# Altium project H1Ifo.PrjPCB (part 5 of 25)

## Sheet IfoIsc1.SchDoc: D1800185
size C; Engineer: Daniel Sigg; DocumentNumber: 4; Revision: 4; SheetNumber: 4; SheetTotal: 11
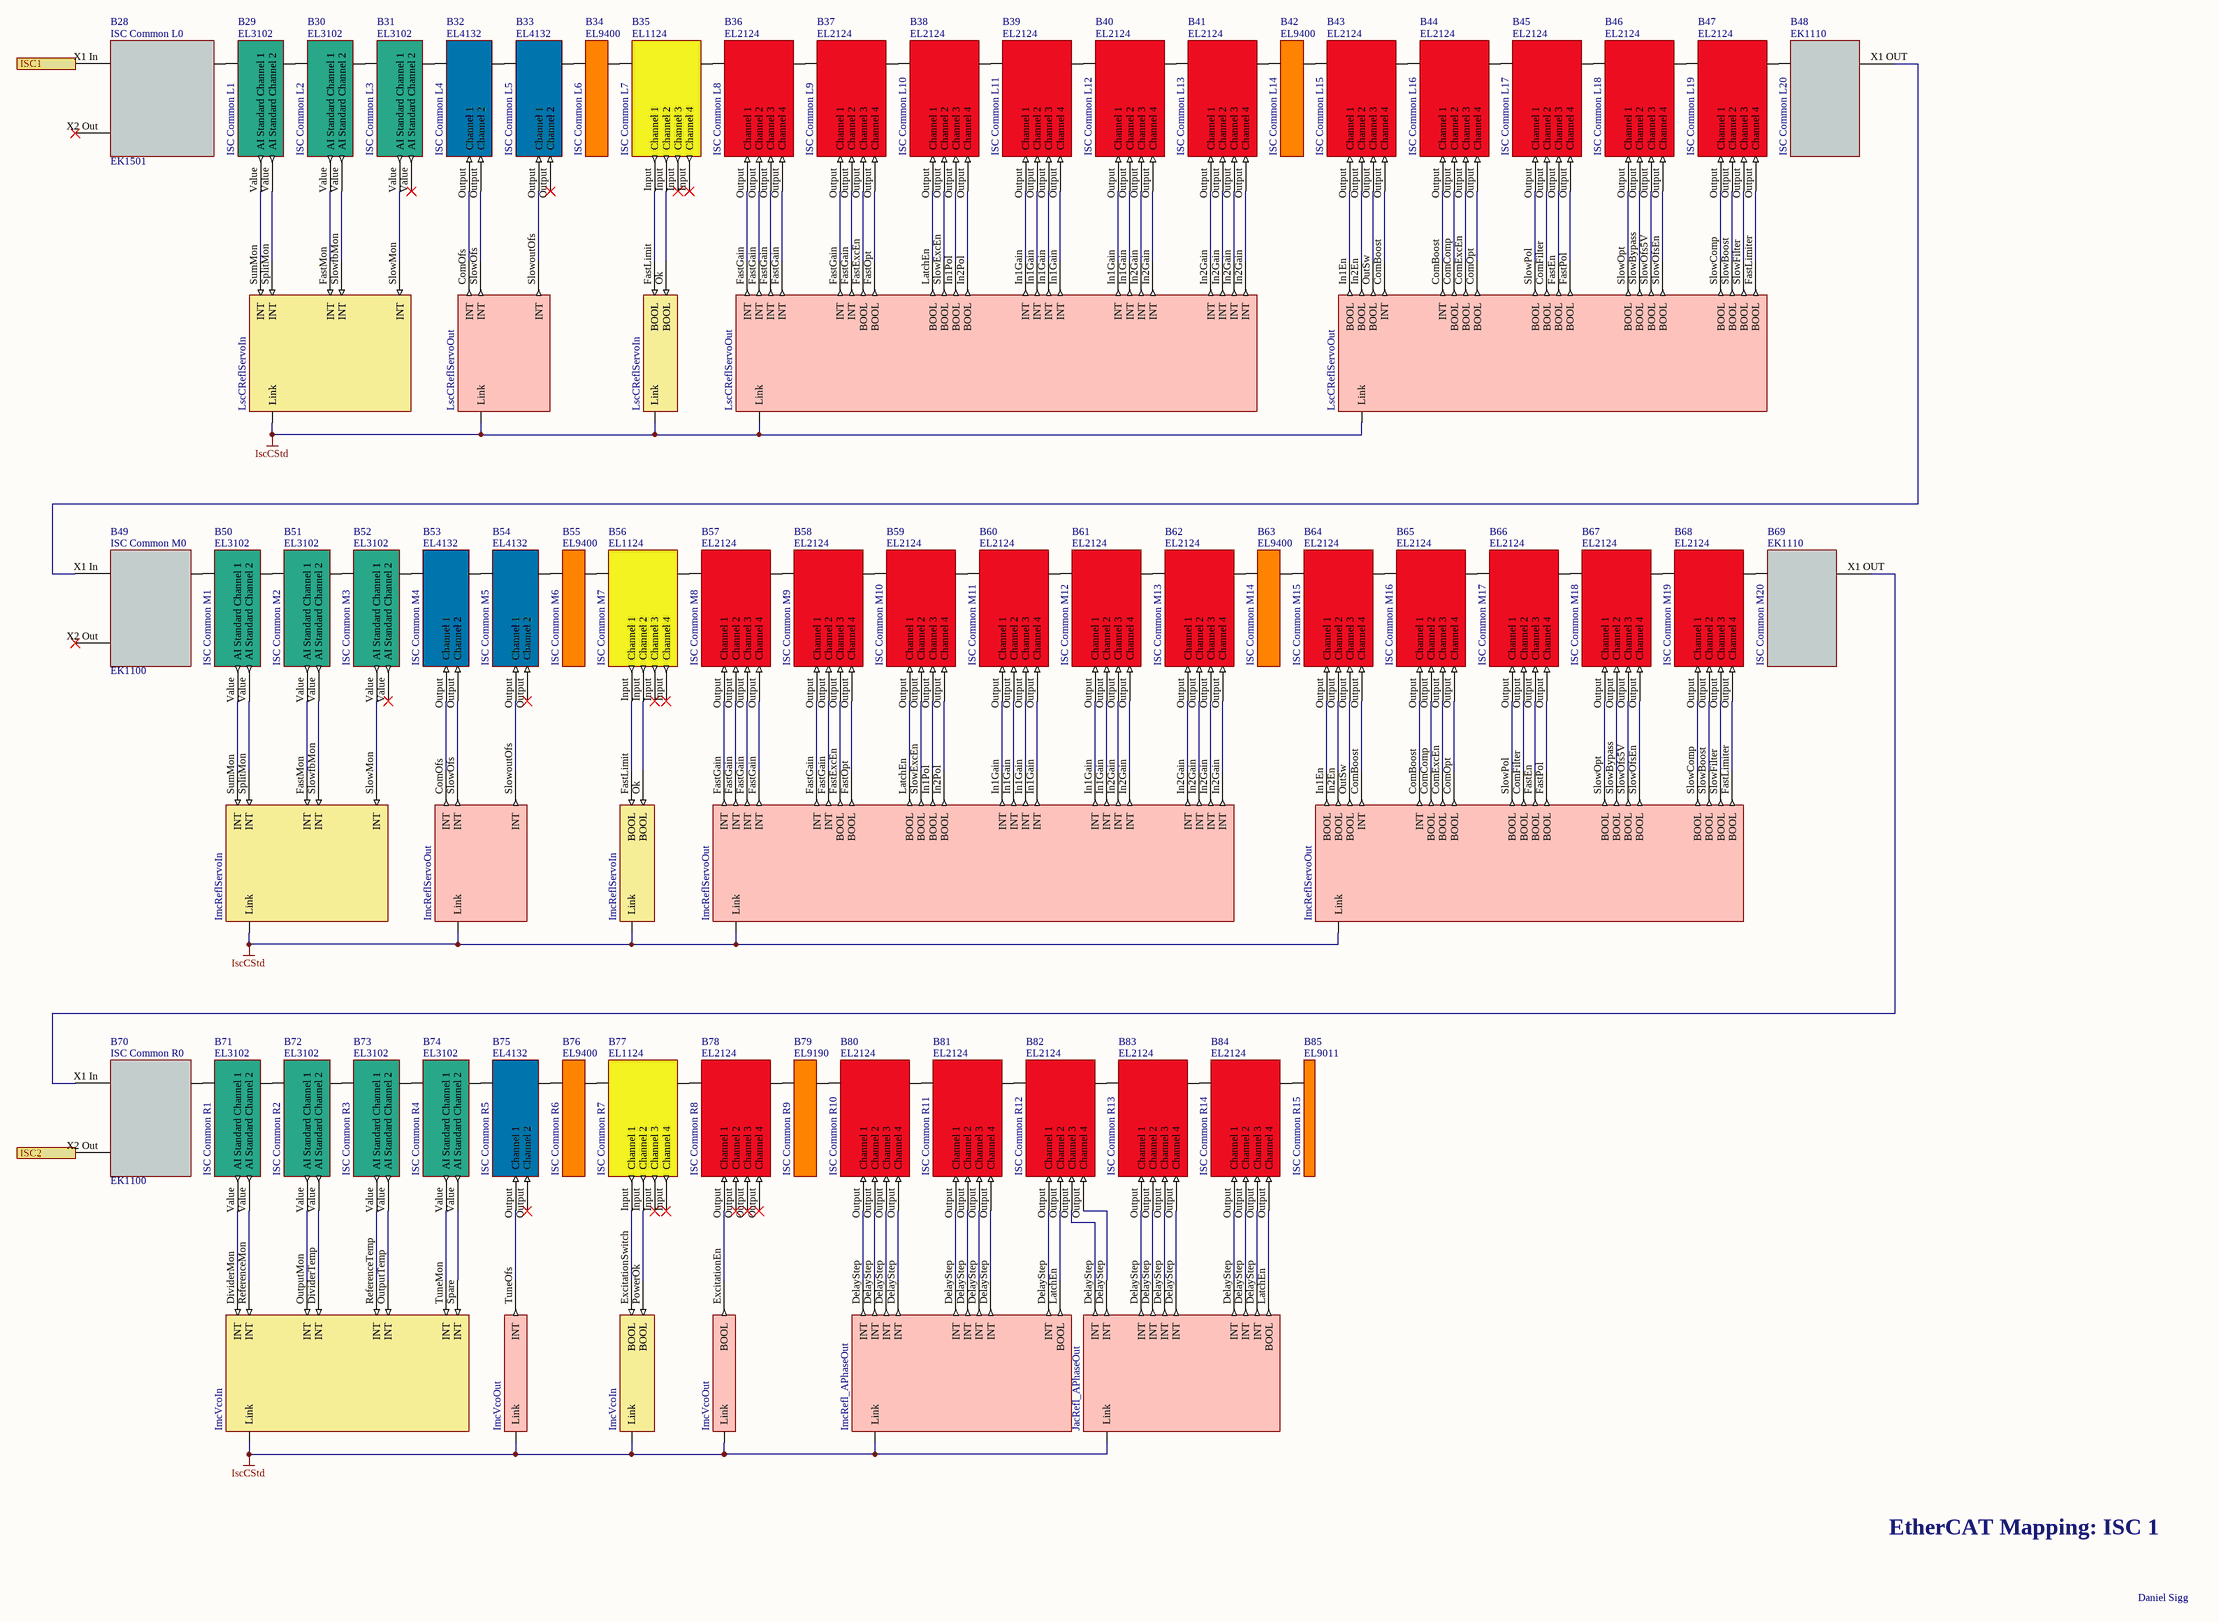
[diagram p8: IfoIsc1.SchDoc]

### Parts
B28  ISC Common L0  Part Number: EK1501  (mechanical)
B29  ISC Common L1  Part Number: EL3102  (mechanical)
B30  ISC Common L2  Part Number: EL3102  (mechanical)
B31  ISC Common L3  Part Number: EL3102  (mechanical)
B32  ISC Common L4  Part Number: EL4132  (mechanical)
B33  ISC Common L5  Part Number: EL4132  (mechanical)
B34  ISC Common L6  Part Number: EL9400  (mechanical)
B35  ISC Common L7  Part Number: EL1124  (mechanical)
B36  ISC Common L8  Part Number: EL2124  (mechanical)
B37  ISC Common L9  Part Number: EL2124  (mechanical)
B38  ISC Common L10  Part Number: EL2124  (mechanical)
B39  ISC Common L11  Part Number: EL2124  (mechanical)
B40  ISC Common L12  Part Number: EL2124  (mechanical)
B41  ISC Common L13  Part Number: EL2124  (mechanical)
B42  ISC Common L14  Part Number: EL9400  (mechanical)
B43  ISC Common L15  Part Number: EL2124  (mechanical)
B44  ISC Common L16  Part Number: EL2124  (mechanical)
B45  ISC Common L17  Part Number: EL2124  (mechanical)
B46  ISC Common L18  Part Number: EL2124  (mechanical)
B47  ISC Common L19  Part Number: EL2124  (mechanical)
B48  ISC Common L20  Part Number: EK1110  (mechanical)
B49  ISC Common M0  Part Number: EK1100  (mechanical)
B50  ISC Common M1  Part Number: EL3102  (mechanical)
B51  ISC Common M2  Part Number: EL3102  (mechanical)
B52  ISC Common M3  Part Number: EL3102  (mechanical)
B53  ISC Common M4  Part Number: EL4132  (mechanical)
B54  ISC Common M5  Part Number: EL4132  (mechanical)
B55  ISC Common M6  Part Number: EL9400  (mechanical)
B56  ISC Common M7  Part Number: EL1124  (mechanical)
B57  ISC Common M8  Part Number: EL2124  (mechanical)
B58  ISC Common M9  Part Number: EL2124  (mechanical)
B59  ISC Common M10  Part Number: EL2124  (mechanical)
B60  ISC Common M11  Part Number: EL2124  (mechanical)
B61  ISC Common M12  Part Number: EL2124  (mechanical)
B62  ISC Common M13  Part Number: EL2124  (mechanical)
B63  ISC Common M14  Part Number: EL9400  (mechanical)
B64  ISC Common M15  Part Number: EL2124  (mechanical)
B65  ISC Common M16  Part Number: EL2124  (mechanical)
B66  ISC Common M17  Part Number: EL2124  (mechanical)
B67  ISC Common M18  Part Number: EL2124  (mechanical)
B68  ISC Common M19  Part Number: EL2124  (mechanical)
B69  ISC Common M20  Part Number: EK1110  (mechanical)
B70  ISC Common R0  Part Number: EK1100  (mechanical)
B71  ISC Common R1  Part Number: EL3102  (mechanical)
B72  ISC Common R2  Part Number: EL3102  (mechanical)
B73  ISC Common R3  Part Number: EL3102  (mechanical)
B74  ISC Common R4  Part Number: EL3102  (mechanical)
B75  ISC Common R5  Part Number: EL4132  (mechanical)
B76  ISC Common R6  Part Number: EL9400  (mechanical)
B77  ISC Common R7  Part Number: EL1124  (mechanical)
B78  ISC Common R8  Part Number: EL2124  (mechanical)
B79  ISC Common R9  Part Number: EL9190  (mechanical)
B80  ISC Common R10  Part Number: EL2124  (mechanical)
B81  ISC Common R11  Part Number: EL2124  (mechanical)
B82  ISC Common R12  Part Number: EL2124  (mechanical)
B83  ISC Common R13  Part Number: EL2124  (mechanical)
B84  ISC Common R14  Part Number: EL2124  (mechanical)
B85  ISC Common R15  Part Number: EL9011  (mechanical)
V68  ImcVcoIn  (parts A,B of 2)  (no BOM)
V144  LscCReflServoIn  (parts A,B of 2)  (no BOM)
V145  LscCReflServoOut  (parts A,B,C of 3)  (no BOM)
V146  ImcReflServoIn  (parts A,B of 2)  (no BOM)
V147  ImcReflServoOut  (parts A,B,C of 3)  (no BOM)
V148  ImcVcoOut  (parts A,B of 2)  (no BOM)
V150  ImcRefl_APhaseOut  (no BOM)
V151  JacRefl_APhaseOut  (no BOM)

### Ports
ISC1, ISC2

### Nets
IscCStd: V68.0(Link) V68.1(Link) V144.1(Link) V144.?1(Link) V145.1(Link) V145.2(Link) V145.?1(Link) V146.1(Link) V146.?1(Link) V147.1(Link) V147.2(Link) V147.?1(Link) V148.0(Link) V148.1(Link) V150.?1(Link) V151.?1(Link)
NetB28_Ebus: B28.Ebus(B) B29.Ebus(A)
NetB28_X1 In: B28.X1_In(A) ; port ISC1
NetB29_Ebus: B29.Ebus(B) B30.Ebus(A)
NetB29_Value: B29.Value(AI_Standard_Channel_1) V144.SumMon(INT)
NetB29_Value: B29.Value(AI_Standard_Channel_2) V144.SplitMon(INT)  [a separate net that carries the same name]
NetB30_Ebus: B30.Ebus(B) B31.Ebus(A)
NetB30_Value: B30.Value(AI_Standard_Channel_1) V144.FastMon(INT)
NetB30_Value: B30.Value(AI_Standard_Channel_2) V144.SlowfbMon(INT)  [a separate net that carries the same name]
NetB31_Ebus: B31.Ebus(B) B32.Ebus(A)
NetB31_Value: B31.Value(AI_Standard_Channel_1) V144.SlowMon(INT)
NetB32_Ebus: B32.Ebus(B) B33.Ebus(A)
NetB32_Output: B32.Output(Channel_1) V145.ComOfs(INT)
NetB32_Output: B32.Output(Channel_2) V145.SlowOfs(INT)  [a separate net that carries the same name]
NetB33_Ebus: B33.Ebus(B) B34.Ebus(A)
NetB33_Output: B33.Output(Channel_1) V145.SlowoutOfs(INT)
NetB34_Ebus: B34.Ebus(B) B35.Ebus(A)
NetB35_Ebus: B35.Ebus(B) B36.Ebus(A)
NetB35_Input: B35.Input(Channel_1) V144.FastLimit(BOOL)
NetB35_Input: B35.Input(Channel_2) V144.Ok(BOOL)  [a separate net that carries the same name]
NetB36_Ebus: B36.Ebus(B) B37.Ebus(A)
NetB36_Output: B36.Output(Channel_1) V145.FastGain(INT)
NetB36_Output: B36.Output(Channel_2) V145.FastGain(INT)  [a separate net that carries the same name]
NetB36_Output: B36.Output(Channel_3) V145.FastGain(INT)  [a separate net that carries the same name]
NetB36_Output: B36.Output(Channel_4) V145.FastGain(INT)  [a separate net that carries the same name]
NetB37_Ebus: B37.Ebus(B) B38.Ebus(A)
NetB37_Output: B37.Output(Channel_1) V145.FastGain(INT)
NetB37_Output: B37.Output(Channel_2) V145.FastGain(INT)  [a separate net that carries the same name]
NetB37_Output: B37.Output(Channel_3) V145.FastExcEn(BOOL)  [a separate net that carries the same name]
NetB37_Output: B37.Output(Channel_4) V145.FastOpt(BOOL)  [a separate net that carries the same name]
NetB38_Ebus: B38.Ebus(B) B39.Ebus(A)
NetB38_Output: B38.Output(Channel_1) V145.LatchEn(BOOL)
NetB38_Output: B38.Output(Channel_2) V145.SlowExcEn(BOOL)  [a separate net that carries the same name]
NetB38_Output: B38.Output(Channel_3) V145.In1Pol(BOOL)  [a separate net that carries the same name]
NetB38_Output: B38.Output(Channel_4) V145.In2Pol(BOOL)  [a separate net that carries the same name]
NetB39_Ebus: B39.Ebus(B) B40.Ebus(A)
NetB39_Output: B39.Output(Channel_1) V145.In1Gain(INT)
NetB39_Output: B39.Output(Channel_2) V145.In1Gain(INT)  [a separate net that carries the same name]
NetB39_Output: B39.Output(Channel_3) V145.In1Gain(INT)  [a separate net that carries the same name]
NetB39_Output: B39.Output(Channel_4) V145.In1Gain(INT)  [a separate net that carries the same name]
NetB40_Ebus: B40.Ebus(B) B41.Ebus(A)
NetB40_Output: B40.Output(Channel_1) V145.In1Gain(INT)
NetB40_Output: B40.Output(Channel_2) V145.In1Gain(INT)  [a separate net that carries the same name]
NetB40_Output: B40.Output(Channel_3) V145.In2Gain(INT)  [a separate net that carries the same name]
NetB40_Output: B40.Output(Channel_4) V145.In2Gain(INT)  [a separate net that carries the same name]
NetB41_Ebus: B41.Ebus(B) B42.Ebus(A)
NetB41_Output: B41.Output(Channel_1) V145.In2Gain(INT)
NetB41_Output: B41.Output(Channel_2) V145.In2Gain(INT)  [a separate net that carries the same name]
NetB41_Output: B41.Output(Channel_3) V145.In2Gain(INT)  [a separate net that carries the same name]
NetB41_Output: B41.Output(Channel_4) V145.In2Gain(INT)  [a separate net that carries the same name]
NetB42_Ebus: B42.Ebus(B) B43.Ebus(A)
NetB43_Ebus: B43.Ebus(B) B44.Ebus(A)
NetB43_Output: B43.Output(Channel_1) V145.In1En(BOOL)
NetB43_Output: B43.Output(Channel_2) V145.In2En(BOOL)  [a separate net that carries the same name]
NetB43_Output: B43.Output(Channel_3) V145.OutSw(BOOL)  [a separate net that carries the same name]
NetB43_Output: B43.Output(Channel_4) V145.ComBoost(INT)  [a separate net that carries the same name]
NetB44_Ebus: B44.Ebus(B) B45.Ebus(A)
NetB44_Output: B44.Output(Channel_1) V145.ComBoost(INT)
NetB44_Output: B44.Output(Channel_2) V145.ComComp(BOOL)  [a separate net that carries the same name]
NetB44_Output: B44.Output(Channel_3) V145.ComExcEn(BOOL)  [a separate net that carries the same name]
NetB44_Output: B44.Output(Channel_4) V145.ComOpt(BOOL)  [a separate net that carries the same name]
NetB45_Ebus: B45.Ebus(B) B46.Ebus(A)
NetB45_Output: B45.Output(Channel_1) V145.SlowPol(BOOL)
NetB45_Output: B45.Output(Channel_2) V145.ComFilter(BOOL)  [a separate net that carries the same name]
NetB45_Output: B45.Output(Channel_3) V145.FastEn(BOOL)  [a separate net that carries the same name]
NetB45_Output: B45.Output(Channel_4) V145.FastPol(BOOL)  [a separate net that carries the same name]
NetB46_Ebus: B46.Ebus(B) B47.Ebus(A)
NetB46_Output: B46.Output(Channel_1) V145.SlowOpt(BOOL)
NetB46_Output: B46.Output(Channel_2) V145.SlowBypass(BOOL)  [a separate net that carries the same name]
NetB46_Output: B46.Output(Channel_3) V145.SlowOfs5V(BOOL)  [a separate net that carries the same name]
NetB46_Output: B46.Output(Channel_4) V145.SlowOfsEn(BOOL)  [a separate net that carries the same name]
NetB47_Ebus: B47.Ebus(B) B48.Ebus(A)
NetB47_Output: B47.Output(Channel_1) V145.SlowComp(BOOL)
NetB47_Output: B47.Output(Channel_2) V145.SlowBoost(BOOL)  [a separate net that carries the same name]
NetB47_Output: B47.Output(Channel_3) V145.SlowFilter(BOOL)  [a separate net that carries the same name]
NetB47_Output: B47.Output(Channel_4) V145.FastLimiter(BOOL)  [a separate net that carries the same name]
NetB48_X1 OUT: B48.X1_OUT(B) B49.X1_In(A)
NetB49_Ebus: B49.Ebus(B) B50.Ebus(A)
NetB50_Ebus: B50.Ebus(B) B51.Ebus(A)
NetB50_Value: B50.Value(AI_Standard_Channel_1) V146.SumMon(INT)
NetB50_Value: B50.Value(AI_Standard_Channel_2) V146.SplitMon(INT)  [a separate net that carries the same name]
NetB51_Ebus: B51.Ebus(B) B52.Ebus(A)
NetB51_Value: B51.Value(AI_Standard_Channel_1) V146.FastMon(INT)
NetB51_Value: B51.Value(AI_Standard_Channel_2) V146.SlowfbMon(INT)  [a separate net that carries the same name]
NetB52_Ebus: B52.Ebus(B) B53.Ebus(A)
NetB52_Value: B52.Value(AI_Standard_Channel_1) V146.SlowMon(INT)
NetB53_Ebus: B53.Ebus(B) B54.Ebus(A)
NetB53_Output: B53.Output(Channel_1) V147.ComOfs(INT)
NetB53_Output: B53.Output(Channel_2) V147.SlowOfs(INT)  [a separate net that carries the same name]
NetB54_Ebus: B54.Ebus(B) B55.Ebus(A)
NetB54_Output: B54.Output(Channel_1) V147.SlowoutOfs(INT)
NetB55_Ebus: B55.Ebus(B) B56.Ebus(A)
NetB56_Ebus: B56.Ebus(B) B57.Ebus(A)
NetB56_Input: B56.Input(Channel_1) V146.FastLimit(BOOL)
NetB56_Input: B56.Input(Channel_2) V146.Ok(BOOL)  [a separate net that carries the same name]
NetB57_Ebus: B57.Ebus(B) B58.Ebus(A)
NetB57_Output: B57.Output(Channel_1) V147.FastGain(INT)
NetB57_Output: B57.Output(Channel_2) V147.FastGain(INT)  [a separate net that carries the same name]
NetB57_Output: B57.Output(Channel_3) V147.FastGain(INT)  [a separate net that carries the same name]
NetB57_Output: B57.Output(Channel_4) V147.FastGain(INT)  [a separate net that carries the same name]
NetB58_Ebus: B58.Ebus(B) B59.Ebus(A)
NetB58_Output: B58.Output(Channel_1) V147.FastGain(INT)
NetB58_Output: B58.Output(Channel_2) V147.FastGain(INT)  [a separate net that carries the same name]
NetB58_Output: B58.Output(Channel_3) V147.FastExcEn(BOOL)  [a separate net that carries the same name]
NetB58_Output: B58.Output(Channel_4) V147.FastOpt(BOOL)  [a separate net that carries the same name]
NetB59_Ebus: B59.Ebus(B) B60.Ebus(A)
NetB59_Output: B59.Output(Channel_1) V147.LatchEn(BOOL)
NetB59_Output: B59.Output(Channel_2) V147.SlowExcEn(BOOL)  [a separate net that carries the same name]
NetB59_Output: B59.Output(Channel_3) V147.In1Pol(BOOL)  [a separate net that carries the same name]
NetB59_Output: B59.Output(Channel_4) V147.In2Pol(BOOL)  [a separate net that carries the same name]
NetB60_Ebus: B60.Ebus(B) B61.Ebus(A)
NetB60_Output: B60.Output(Channel_1) V147.In1Gain(INT)
NetB60_Output: B60.Output(Channel_2) V147.In1Gain(INT)  [a separate net that carries the same name]
NetB60_Output: B60.Output(Channel_3) V147.In1Gain(INT)  [a separate net that carries the same name]
NetB60_Output: B60.Output(Channel_4) V147.In1Gain(INT)  [a separate net that carries the same name]
NetB61_Ebus: B61.Ebus(B) B62.Ebus(A)
NetB61_Output: B61.Output(Channel_1) V147.In1Gain(INT)
NetB61_Output: B61.Output(Channel_2) V147.In1Gain(INT)  [a separate net that carries the same name]
NetB61_Output: B61.Output(Channel_3) V147.In2Gain(INT)  [a separate net that carries the same name]
NetB61_Output: B61.Output(Channel_4) V147.In2Gain(INT)  [a separate net that carries the same name]
NetB62_Ebus: B62.Ebus(B) B63.Ebus(A)
NetB62_Output: B62.Output(Channel_1) V147.In2Gain(INT)
NetB62_Output: B62.Output(Channel_2) V147.In2Gain(INT)  [a separate net that carries the same name]
NetB62_Output: B62.Output(Channel_3) V147.In2Gain(INT)  [a separate net that carries the same name]
NetB62_Output: B62.Output(Channel_4) V147.In2Gain(INT)  [a separate net that carries the same name]
NetB63_Ebus: B63.Ebus(B) B64.Ebus(A)
NetB64_Ebus: B64.Ebus(B) B65.Ebus(A)
NetB64_Output: B64.Output(Channel_1) V147.In1En(BOOL)
NetB64_Output: B64.Output(Channel_2) V147.In2En(BOOL)  [a separate net that carries the same name]
NetB64_Output: B64.Output(Channel_3) V147.OutSw(BOOL)  [a separate net that carries the same name]
NetB64_Output: B64.Output(Channel_4) V147.ComBoost(INT)  [a separate net that carries the same name]
NetB65_Ebus: B65.Ebus(B) B66.Ebus(A)
NetB65_Output: B65.Output(Channel_1) V147.ComBoost(INT)
NetB65_Output: B65.Output(Channel_2) V147.ComComp(BOOL)  [a separate net that carries the same name]
NetB65_Output: B65.Output(Channel_3) V147.ComExcEn(BOOL)  [a separate net that carries the same name]
NetB65_Output: B65.Output(Channel_4) V147.ComOpt(BOOL)  [a separate net that carries the same name]
NetB66_Ebus: B66.Ebus(B) B67.Ebus(A)
NetB66_Output: B66.Output(Channel_1) V147.SlowPol(BOOL)
NetB66_Output: B66.Output(Channel_2) V147.ComFilter(BOOL)  [a separate net that carries the same name]
NetB66_Output: B66.Output(Channel_3) V147.FastEn(BOOL)  [a separate net that carries the same name]
NetB66_Output: B66.Output(Channel_4) V147.FastPol(BOOL)  [a separate net that carries the same name]
NetB67_Ebus: B67.Ebus(B) B68.Ebus(A)
NetB67_Output: B67.Output(Channel_1) V147.SlowOpt(BOOL)
NetB67_Output: B67.Output(Channel_2) V147.SlowBypass(BOOL)  [a separate net that carries the same name]
NetB67_Output: B67.Output(Channel_3) V147.SlowOfs5V(BOOL)  [a separate net that carries the same name]
NetB67_Output: B67.Output(Channel_4) V147.SlowOfsEn(BOOL)  [a separate net that carries the same name]
NetB68_Ebus: B68.Ebus(B) B69.Ebus(A)
NetB68_Output: B68.Output(Channel_1) V147.SlowComp(BOOL)
NetB68_Output: B68.Output(Channel_2) V147.SlowBoost(BOOL)  [a separate net that carries the same name]
NetB68_Output: B68.Output(Channel_3) V147.SlowFilter(BOOL)  [a separate net that carries the same name]
NetB68_Output: B68.Output(Channel_4) V147.FastLimiter(BOOL)  [a separate net that carries the same name]
NetB69_X1 OUT: B69.X1_OUT(B) B70.X1_In(A)
NetB70_Ebus: B70.Ebus(B) B71.Ebus(A)
NetB70_X2 Out: B70.X2_Out(C) ; port ISC2
NetB71_Ebus: B71.Ebus(B) B72.Ebus(A)
NetB71_Value: B71.Value(AI_Standard_Channel_1) V68.DividerMon(INT)
NetB71_Value: B71.Value(AI_Standard_Channel_2) V68.ReferenceMon(INT)  [a separate net that carries the same name]
NetB72_Ebus: B72.Ebus(B) B73.Ebus(A)
NetB72_Value: B72.Value(AI_Standard_Channel_1) V68.OutputMon(INT)
NetB72_Value: B72.Value(AI_Standard_Channel_2) V68.DividerTemp(INT)  [a separate net that carries the same name]
NetB73_Ebus: B73.Ebus(B) B74.Ebus(A)
NetB73_Value: B73.Value(AI_Standard_Channel_1) V68.ReferenceTemp(INT)
NetB73_Value: B73.Value(AI_Standard_Channel_2) V68.OutputTemp(INT)  [a separate net that carries the same name]
NetB74_Ebus: B74.Ebus(B) B75.Ebus(A)
NetB74_Value: B74.Value(AI_Standard_Channel_1) V68.TuneMon(INT)
NetB74_Value: B74.Value(AI_Standard_Channel_2) V68.Spare(INT)  [a separate net that carries the same name]
NetB75_Ebus: B75.Ebus(B) B76.Ebus(A)
NetB75_Output: B75.Output(Channel_1) V148.TuneOfs(INT)
NetB76_Ebus: B76.Ebus(B) B77.Ebus(A)
NetB77_Ebus: B77.Ebus(B) B78.Ebus(A)
NetB77_Input: B77.Input(Channel_1) V68.ExcitationSwitch(BOOL)
NetB77_Input: B77.Input(Channel_2) V68.PowerOk(BOOL)  [a separate net that carries the same name]
NetB78_Ebus: B78.Ebus(B) B79.Ebus(A)
NetB78_Output: B78.Output(Channel_1) V148.ExcitationEn(BOOL)
NetB79_Ebus: B79.Ebus(B) B80.Ebus(A)
NetB80_Ebus: B80.Ebus(B) B81.Ebus(A)
NetB80_Output: B80.Output(Channel_1) V150.DelayStep(INT)
NetB80_Output: B80.Output(Channel_2) V150.DelayStep(INT)  [a separate net that carries the same name]
NetB80_Output: B80.Output(Channel_3) V150.DelayStep(INT)  [a separate net that carries the same name]
NetB80_Output: B80.Output(Channel_4) V150.DelayStep(INT)  [a separate net that carries the same name]
NetB81_Ebus: B81.Ebus(B) B82.Ebus(A)
NetB81_Output: B81.Output(Channel_1) V150.DelayStep(INT)
NetB81_Output: B81.Output(Channel_2) V150.DelayStep(INT)  [a separate net that carries the same name]
NetB81_Output: B81.Output(Channel_3) V150.DelayStep(INT)  [a separate net that carries the same name]
NetB81_Output: B81.Output(Channel_4) V150.DelayStep(INT)  [a separate net that carries the same name]
NetB82_Ebus: B82.Ebus(B) B83.Ebus(A)
NetB82_Output: B82.Output(Channel_1) V150.DelayStep(INT)
NetB82_Output: B82.Output(Channel_2) V150.LatchEn(BOOL)  [a separate net that carries the same name]
NetB82_Output: B82.Output(Channel_3) V151.DelayStep(INT)  [a separate net that carries the same name]
NetB82_Output: B82.Output(Channel_4) V151.DelayStep(INT)  [a separate net that carries the same name]
NetB83_Ebus: B83.Ebus(B) B84.Ebus(A)
NetB83_Output: B83.Output(Channel_1) V151.DelayStep(INT)
NetB83_Output: B83.Output(Channel_2) V151.DelayStep(INT)  [a separate net that carries the same name]
NetB83_Output: B83.Output(Channel_3) V151.DelayStep(INT)  [a separate net that carries the same name]
NetB83_Output: B83.Output(Channel_4) V151.DelayStep(INT)  [a separate net that carries the same name]
NetB84_Ebus: B84.Ebus(B) B85.Ebus(A)
NetB84_Output: B84.Output(Channel_1) V151.DelayStep(INT)
NetB84_Output: B84.Output(Channel_2) V151.DelayStep(INT)  [a separate net that carries the same name]
NetB84_Output: B84.Output(Channel_3) V151.DelayStep(INT)  [a separate net that carries the same name]
NetB84_Output: B84.Output(Channel_4) V151.LatchEn(BOOL)  [a separate net that carries the same name]

Not connected (* = marked no-connect by the designer): B28 X2 Out(C)*; B49 X2 Out(C)*

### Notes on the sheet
- EtherCAT Mapping: ISC 1
- Daniel Sigg

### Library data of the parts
B28 = CouplerEK1501: Fiber Coupler; Rail: Left; BoxNextB: UWGNJJDY; BoxPrev: IQKGWTEC; PortPrevFull: 1001/B; PortPrevShort: B 'X1'; Fullname: TIID^Vertex ISC (EtherCAT)^ISC Common L0 (EK1501); BoxPorts: Junction; BoxAddr: 1002; Disabled: False
B29 = TerminalEL3102: EtherCAT Terminal EL3102 2-chn Analog Input; Rail: Left; BoxNextB: QKLDDUHA; BoxPrev: SGTCQRGF; PortPrevFull: 1002/B; PortPrevShort: B; Fullname: TIID^Vertex ISC (EtherCAT)^ISC Common L0 (EK1501)^ISC Common L1 (EL3102); BoxAddr: 1003; Disabled: False
B30 = TerminalEL3102: EtherCAT Terminal EL3102 2-chn Analog Input; Rail: Left; BoxNextB: GASJWKJA; BoxPrev: UWGNJJDY; PortPrevFull: 1003/B; PortPrevShort: B; Fullname: TIID^Vertex ISC (EtherCAT)^ISC Common L0 (EK1501)^ISC Common L2 (EL3102); BoxAddr: 1004; Disabled: False
B31 = TerminalEL3102: EtherCAT Terminal EL3102 2-chn Analog Input; Rail: Left; BoxNextB: VOTCLVTA; BoxPrev: QKLDDUHA; PortPrevFull: 1004/B; PortPrevShort: B; Fullname: TIID^Vertex ISC (EtherCAT)^ISC Common L0 (EK1501)^ISC Common L3 (EL3102); BoxAddr: 1005; Disabled: False
B32 = TerminalEL4132: EtherCAT Terminal EL4132 2-chn Analog Ouput; Rail: Left; BoxNextB: URCARDTW; BoxPrev: GASJWKJA; PortPrevFull: 1005/B; PortPrevShort: B; Fullname: TIID^Vertex ISC (EtherCAT)^ISC Common L0 (EK1501)^ISC Common L4 (EL4132); BoxAddr: 1006; Disabled: False
B33 = TerminalEL4132: EtherCAT Terminal EL4132 2-chn Analog Ouput; Rail: Left; BoxNextB: GMNEQLSB; BoxPrev: VOTCLVTA; PortPrevFull: 1006/B; PortPrevShort: B; Fullname: TIID^Vertex ISC (EtherCAT)^ISC Common L0 (EK1501)^ISC Common L5 (EL4132); BoxAddr: 1007; Disabled: False
B34 = TerminalEL9400: EtherCAT Terminal EL9400 Power; BoxType: TerminalPassive; Rail: Left; BoxNextB: ETQIOKIX; BoxPrev: URCARDTW; PortPrevShort: B; Fullname: TIID^Vertex ISC (EtherCAT)^ISC Common L0 (EK1501)^ISC Common L6 (EL9400); Disabled: False
B35 = TerminalEL1124: EtherCAT Terminal EL1124 4-chn Digital Input; Rail: Left; BoxNextB: RASRJBOQ; BoxPrev: GMNEQLSB; PortPrevFull: 1007/B; PortPrevShort: B; Fullname: TIID^Vertex ISC (EtherCAT)^ISC Common L0 (EK1501)^ISC Common L7 (EL1124); BoxAddr: 1008; Disabled: False
B36 = TerminalEL2124: EtherCAT Terminal EL2124 4-chn Digital Ouput; Rail: Left; BoxNextB: IAJGLJHS; BoxPrev: ETQIOKIX; PortPrevFull: 1008/B; PortPrevShort: B; Fullname: TIID^Vertex ISC (EtherCAT)^ISC Common L0 (EK1501)^ISC Common L8 (EL2124); BoxAddr: 1009; Disabled: False
B37 = TerminalEL2124: EtherCAT Terminal EL2124 4-chn Digital Ouput; Rail: Left; BoxNextB: NPTVUSKY; BoxPrev: RASRJBOQ; PortPrevFull: 1009/B; PortPrevShort: B; Fullname: TIID^Vertex ISC (EtherCAT)^ISC Common L0 (EK1501)^ISC Common L9 (EL2124); BoxAddr: 1010; Disabled: False
B38 = TerminalEL2124: EtherCAT Terminal EL2124 4-chn Digital Ouput; Rail: Left; BoxNextB: UEOUYOEM; BoxPrev: IAJGLJHS; PortPrevFull: 1010/B; PortPrevShort: B; Fullname: TIID^Vertex ISC (EtherCAT)^ISC Common L0 (EK1501)^ISC Common L10 (EL2124); BoxAddr: 1011; Disabled: False
B39 = TerminalEL2124: EtherCAT Terminal EL2124 4-chn Digital Ouput; Rail: Left; BoxNextB: NGRHYCIY; BoxPrev: NPTVUSKY; PortPrevFull: 1011/B; PortPrevShort: B; Fullname: TIID^Vertex ISC (EtherCAT)^ISC Common L0 (EK1501)^ISC Common L11 (EL2124); BoxAddr: 1012; Disabled: False
B40 = TerminalEL2124: EtherCAT Terminal EL2124 4-chn Digital Ouput; Rail: Left; BoxNextB: KNVNTRMC; BoxPrev: UEOUYOEM; PortPrevFull: 1012/B; PortPrevShort: B; Fullname: TIID^Vertex ISC (EtherCAT)^ISC Common L0 (EK1501)^ISC Common L12 (EL2124); BoxAddr: 1013; Disabled: False
B41 = TerminalEL2124: EtherCAT Terminal EL2124 4-chn Digital Ouput; Rail: Left; BoxNextB: FGMEICSD; BoxPrev: NGRHYCIY; PortPrevFull: 1013/B; PortPrevShort: B; Fullname: TIID^Vertex ISC (EtherCAT)^ISC Common L0 (EK1501)^ISC Common L13 (EL2124); BoxAddr: 1014; Disabled: False
B42 = TerminalEL9400: EtherCAT Terminal EL9400 Power; BoxType: TerminalPassive; Rail: Left; BoxNextB: NRKFMSXC; BoxPrev: KNVNTRMC; PortPrevShort: B; Fullname: TIID^Vertex ISC (EtherCAT)^ISC Common L0 (EK1501)^ISC Common L14 (EL9400); Disabled: False
B43 = TerminalEL2124: EtherCAT Terminal EL2124 4-chn Digital Ouput; Rail: Left; BoxNextB: IVPEGGTT; BoxPrev: FGMEICSD; PortPrevFull: 1014/B; PortPrevShort: B; Fullname: TIID^Vertex ISC (EtherCAT)^ISC Common L0 (EK1501)^ISC Common L15 (EL2124); BoxAddr: 1015; Disabled: False
B44 = TerminalEL2124: EtherCAT Terminal EL2124 4-chn Digital Ouput; Rail: Left; BoxNextB: LIEIFPDV; BoxPrev: NRKFMSXC; PortPrevFull: 1015/B; PortPrevShort: B; Fullname: TIID^Vertex ISC (EtherCAT)^ISC Common L0 (EK1501)^ISC Common L16 (EL2124); BoxAddr: 1016; Disabled: False
B45 = TerminalEL2124: EtherCAT Terminal EL2124 4-chn Digital Ouput; Rail: Left; BoxNextB: EEFDTLTD; BoxPrev: IVPEGGTT; PortPrevFull: 1016/B; PortPrevShort: B; Fullname: TIID^Vertex ISC (EtherCAT)^ISC Common L0 (EK1501)^ISC Common L17 (EL2124); BoxAddr: 1017; Disabled: False
B46 = TerminalEL2124: EtherCAT Terminal EL2124 4-chn Digital Ouput; Rail: Left; BoxNextB: CYELLGAO; BoxPrev: LIEIFPDV; PortPrevFull: 1017/B; PortPrevShort: B; Fullname: TIID^Vertex ISC (EtherCAT)^ISC Common L0 (EK1501)^ISC Common L18 (EL2124); BoxAddr: 1018; Disabled: False
B47 = TerminalEL2124: EtherCAT Terminal EL2124 4-chn Digital Ouput; Rail: Left; BoxNextB: KXQOEVIP; BoxPrev: EEFDTLTD; PortPrevFull: 1018/B; PortPrevShort: B; Fullname: TIID^Vertex ISC (EtherCAT)^ISC Common L0 (EK1501)^ISC Common L19 (EL2124); BoxAddr: 1019; Disabled: False
B48 = CouplerEK1110: EtherCAT Coupler Extension; BoxType: Terminal; Rail: Left; BoxNextB: WNGIOERB; BoxPrev: CYELLGAO; PortPrevFull: 1019/B; PortPrevShort: B; Fullname: TIID^Vertex ISC (EtherCAT)^ISC Common L0 (EK1501)^ISC Common L20 (EK1110); BoxAddr: 1020; Disabled: False
B49 = CouplerEK1100: EtherCAT Coupler; Rail: Middle; BoxNextB: HDQQPKWB; BoxPrev: KXQOEVIP; PortPrevFull: 1020/B; PortPrevShort: B 'X1 OUT'; Fullname: TIID^Vertex ISC (EtherCAT)^ISC Common M0 (EK1100); BoxPorts: Junction; BoxAddr: 1021; Disabled: False
B50 = TerminalEL3102: EtherCAT Terminal EL3102 2-chn Analog Input; Rail: Middle; BoxNextB: EMXYTWNJ; BoxPrev: WNGIOERB; PortPrevFull: 1021/B; PortPrevShort: B; Fullname: TIID^Vertex ISC (EtherCAT)^ISC Common M0 (EK1100)^ISC Common M1 (EL3102); BoxAddr: 1022; Disabled: False; Init1Comment: Set filter for 60Hz
B51 = TerminalEL3102: EtherCAT Terminal EL3102 2-chn Analog Input; Rail: Middle; BoxNextB: QLTHVPSC; BoxPrev: HDQQPKWB; PortPrevFull: 1022/B; PortPrevShort: B; Fullname: TIID^Vertex ISC (EtherCAT)^ISC Common M0 (EK1100)^ISC Common M2 (EL3102); BoxAddr: 1023; Disabled: False
B52 = TerminalEL3102: EtherCAT Terminal EL3102 2-chn Analog Input; Rail: Middle; BoxNextB: NEHLKGTA; BoxPrev: EMXYTWNJ; PortPrevFull: 1023/B; PortPrevShort: B; Fullname: TIID^Vertex ISC (EtherCAT)^ISC Common M0 (EK1100)^ISC Common M3 (EL3102); BoxAddr: 1024; Disabled: False
B53 = TerminalEL4132: EtherCAT Terminal EL4132 2-chn Analog Ouput; Rail: Middle; BoxNextB: QNNAEFJB; BoxPrev: QLTHVPSC; PortPrevFull: 1024/B; PortPrevShort: B; Fullname: TIID^Vertex ISC (EtherCAT)^ISC Common M0 (EK1100)^ISC Common M4 (EL4132); BoxAddr: 1025; Disabled: False
B54 = TerminalEL4132: EtherCAT Terminal EL4132 2-chn Analog Ouput; Rail: Middle; BoxNextB: MAPVLBDV; BoxPrev: NEHLKGTA; PortPrevFull: 1025/B; PortPrevShort: B; Fullname: TIID^Vertex ISC (EtherCAT)^ISC Common M0 (EK1100)^ISC Common M5 (EL4132); BoxAddr: 1026; Disabled: False
B55 = TerminalEL9400: EtherCAT Terminal EL9400 Power; BoxType: TerminalPassive; Rail: Middle; BoxNextB: PYFAXWXH; BoxPrev: QNNAEFJB; PortPrevShort: B; Fullname: TIID^Vertex ISC (EtherCAT)^ISC Common M0 (EK1100)^ISC Common M6 (EL9400); Disabled: False
B56 = TerminalEL1124: EtherCAT Terminal EL1124 4-chn Digital Input; Rail: Middle; BoxNextB: YGWWTAJJ; BoxPrev: MAPVLBDV; PortPrevFull: 1026/B; PortPrevShort: B; Fullname: TIID^Vertex ISC (EtherCAT)^ISC Common M0 (EK1100)^ISC Common M7 (EL1124); BoxAddr: 1027; Disabled: False
B57 = TerminalEL2124: EtherCAT Terminal EL2124 4-chn Digital Ouput; Rail: Middle; BoxNextB: KCTWXWFB; BoxPrev: PYFAXWXH; PortPrevFull: 1027/B; PortPrevShort: B; Fullname: TIID^Vertex ISC (EtherCAT)^ISC Common M0 (EK1100)^ISC Common M8 (EL2124); BoxAddr: 1028; Disabled: False
B58 = TerminalEL2124: EtherCAT Terminal EL2124 4-chn Digital Ouput; Rail: Middle; BoxNextB: WMUGHXMR; BoxPrev: YGWWTAJJ; PortPrevFull: 1028/B; PortPrevShort: B; Fullname: TIID^Vertex ISC (EtherCAT)^ISC Common M0 (EK1100)^ISC Common M9 (EL2124); BoxAddr: 1029; Disabled: False
B59 = TerminalEL2124: EtherCAT Terminal EL2124 4-chn Digital Ouput; Rail: Middle; BoxNextB: ASAMXAFG; BoxPrev: KCTWXWFB; PortPrevFull: 1029/B; PortPrevShort: B; Fullname: TIID^Vertex ISC (EtherCAT)^ISC Common M0 (EK1100)^ISC Common M10 (EL2124); BoxAddr: 1030; Disabled: False
B60 = TerminalEL2124: EtherCAT Terminal EL2124 4-chn Digital Ouput; Rail: Middle; BoxNextB: ETLAVCGS; BoxPrev: WMUGHXMR; PortPrevFull: 1030/B; PortPrevShort: B; Fullname: TIID^Vertex ISC (EtherCAT)^ISC Common M0 (EK1100)^ISC Common M11 (EL2124); BoxAddr: 1031; Disabled: False
B61 = TerminalEL2124: EtherCAT Terminal EL2124 4-chn Digital Ouput; Rail: Middle; BoxNextB: EUNPRYDA; BoxPrev: ASAMXAFG; PortPrevFull: 1031/B; PortPrevShort: B; Fullname: TIID^Vertex ISC (EtherCAT)^ISC Common M0 (EK1100)^ISC Common M12 (EL2124); BoxAddr: 1032; Disabled: False
B62 = TerminalEL2124: EtherCAT Terminal EL2124 4-chn Digital Ouput; Rail: Middle; BoxNextB: HWIBMDFV; BoxPrev: ETLAVCGS; PortPrevFull: 1032/B; PortPrevShort: B; Fullname: TIID^Vertex ISC (EtherCAT)^ISC Common M0 (EK1100)^ISC Common M13 (EL2124); BoxAddr: 1033; Disabled: False
B63 = TerminalEL9400: EtherCAT Terminal EL9400 Power; BoxType: TerminalPassive; Rail: Middle; BoxNextB: EBDFHENJ; BoxPrev: EUNPRYDA; PortPrevShort: B; Fullname: TIID^Vertex ISC (EtherCAT)^ISC Common M0 (EK1100)^ISC Common M14 (EL9400); Disabled: False
B64 = TerminalEL2124: EtherCAT Terminal EL2124 4-chn Digital Ouput; Rail: Middle; BoxNextB: UNMLNLGP; BoxPrev: HWIBMDFV; PortPrevFull: 1033/B; PortPrevShort: B; Fullname: TIID^Vertex ISC (EtherCAT)^ISC Common M0 (EK1100)^ISC Common M15 (EL2124); BoxAddr: 1034; Disabled: False
B65 = TerminalEL2124: EtherCAT Terminal EL2124 4-chn Digital Ouput; Rail: Middle; BoxNextB: CNSPUYQQ; BoxPrev: EBDFHENJ; PortPrevFull: 1034/B; PortPrevShort: B; Fullname: TIID^Vertex ISC (EtherCAT)^ISC Common M0 (EK1100)^ISC Common M16 (EL2124); BoxAddr: 1035; Disabled: False
B66 = TerminalEL2124: EtherCAT Terminal EL2124 4-chn Digital Ouput; Rail: Middle; BoxNextB: HNJKRDES; BoxPrev: UNMLNLGP; PortPrevFull: 1035/B; PortPrevShort: B; Fullname: TIID^Vertex ISC (EtherCAT)^ISC Common M0 (EK1100)^ISC Common M17 (EL2124); BoxAddr: 1036; Disabled: False
B67 = TerminalEL2124: EtherCAT Terminal EL2124 4-chn Digital Ouput; Rail: Middle; BoxNextB: LOOQOHKV; BoxPrev: CNSPUYQQ; PortPrevFull: 1036/B; PortPrevShort: B; Fullname: TIID^Vertex ISC (EtherCAT)^ISC Common M0 (EK1100)^ISC Common M18 (EL2124); BoxAddr: 1037; Disabled: False
B68 = TerminalEL2124: EtherCAT Terminal EL2124 4-chn Digital Ouput; Rail: Middle; BoxNextB: CDURETAU; BoxPrev: HNJKRDES; PortPrevFull: 1037/B; PortPrevShort: B; Fullname: TIID^Vertex ISC (EtherCAT)^ISC Common M0 (EK1100)^ISC Common M19 (EL2124); BoxAddr: 1038; Disabled: False
B69 = CouplerEK1110: EtherCAT Coupler Extension; BoxType: Terminal; Rail: Middle; BoxNextB: YDVXWSMS; BoxPrev: LOOQOHKV; PortPrevFull: 1038/B; PortPrevShort: B; Fullname: TIID^Vertex ISC (EtherCAT)^ISC Common M0 (EK1100)^ISC Common M20 (EK1110); BoxAddr: 1039; Disabled: False
B70 = CouplerEK1100: EtherCAT Coupler; Rail: Right; BoxNextB: AHCXVPKG; BoxNextC: PLVGYVWB; BoxPrev: CDURETAU; PortPrevFull: 1039/B; PortPrevShort: B 'X1 OUT'; Fullname: TIID^Vertex ISC (EtherCAT)^ISC Common R0 (EK1100); BoxPorts: Junction; BoxAddr: 1040; Disabled: False
B71 = TerminalEL3102: EtherCAT Terminal EL3102 2-chn Analog Input; Rail: Right; BoxNextB: LSHAHMDM; BoxPrev: YDVXWSMS; PortPrevFull: 1040/B; PortPrevShort: B; Fullname: TIID^Vertex ISC (EtherCAT)^ISC Common R0 (EK1100)^ISC Common R1 (EL3102); BoxAddr: 1041; Disabled: False
B72 = TerminalEL3102: EtherCAT Terminal EL3102 2-chn Analog Input; Rail: Right; BoxNextB: MOPAMRCV; BoxPrev: AHCXVPKG; PortPrevFull: 1041/B; PortPrevShort: B; Fullname: TIID^Vertex ISC (EtherCAT)^ISC Common R0 (EK1100)^ISC Common R2 (EL3102); BoxAddr: 1042; Disabled: False
B73 = TerminalEL3102: EtherCAT Terminal EL3102 2-chn Analog Input; Rail: Right; BoxNextB: KAWOQVWL; BoxPrev: LSHAHMDM; PortPrevFull: 1042/B; PortPrevShort: B; Fullname: TIID^Vertex ISC (EtherCAT)^ISC Common R0 (EK1100)^ISC Common R3 (EL3102); BoxAddr: 1043; Disabled: False
B74 = TerminalEL3102: EtherCAT Terminal EL3102 2-chn Analog Input; Rail: Right; BoxNextB: NEAGJDCC; BoxPrev: MOPAMRCV; PortPrevFull: 1043/B; PortPrevShort: B; Fullname: TIID^Vertex ISC (EtherCAT)^ISC Common R0 (EK1100)^ISC Common R4 (EL3102); BoxAddr: 1044; Disabled: False
B75 = TerminalEL4132: EtherCAT Terminal EL4132 2-chn Analog Ouput; Rail: Right; BoxNextB: OUGJPVPT; BoxPrev: KAWOQVWL; PortPrevFull: 1044/B; PortPrevShort: B; Fullname: TIID^Vertex ISC (EtherCAT)^ISC Common R0 (EK1100)^ISC Common R5 (EL4132); BoxAddr: 1045; Disabled: False
B76 = TerminalEL9400: EtherCAT Terminal EL9400 Power; BoxType: TerminalPassive; Rail: Right; BoxNextB: UREMANJE; BoxPrev: NEAGJDCC; PortPrevShort: B; Fullname: TIID^Vertex ISC (EtherCAT)^ISC Common R0 (EK1100)^ISC Common R6 (EL9400); Disabled: False
B77 = TerminalEL1124: EtherCAT Terminal EL1124 4-chn Digital Input; Rail: Right; BoxNextB: BBSXQHUG; BoxPrev: OUGJPVPT; PortPrevFull: 1045/B; PortPrevShort: B; Fullname: TIID^Vertex ISC (EtherCAT)^ISC Common R0 (EK1100)^ISC Common R7 (EL1124); BoxAddr: 1046; Disabled: False
B78 = TerminalEL2124: EtherCAT Terminal EL2124 4-chn Digital Ouput; Rail: Right; BoxNextB: CGMWKRVE; BoxPrev: UREMANJE; PortPrevFull: 1046/B; PortPrevShort: B; Fullname: TIID^Vertex ISC (EtherCAT)^ISC Common R0 (EK1100)^ISC Common R8 (EL2124); BoxAddr: 1047; Disabled: False
B79 = TerminalEL9190: EtherCAT Terminal EL9190 Supply; BoxType: TerminalPassive; Rail: Right; BoxNextB: VTQDBUTN; BoxPrev: BBSXQHUG; PortPrevShort: B; Fullname: TIID^Vertex ISC (EtherCAT)^ISC Common R0 (EK1100)^ISC Common R9 (EL9190); Disabled: False
B80 = TerminalEL2124: EtherCAT Terminal EL2124 4-chn Digital Ouput; Rail: Right; BoxNextB: CIPRNNJE; BoxPrev: CGMWKRVE; PortPrevFull: 1047/B; PortPrevShort: B; Fullname: TIID^Vertex ISC (EtherCAT)^ISC Common R0 (EK1100)^ISC Common R10 (EL2124); BoxAddr: 1048; Disabled: False
B81 = TerminalEL2124: EtherCAT Terminal EL2124 4-chn Digital Ouput; Rail: Right; BoxNextB: BQHYSPEL; BoxPrev: VTQDBUTN; PortPrevFull: 1048/B; PortPrevShort: B; Fullname: TIID^Vertex ISC (EtherCAT)^ISC Common R0 (EK1100)^ISC Common R11 (EL2124); BoxAddr: 1049; Disabled: False
B82 = TerminalEL2124: EtherCAT Terminal EL2124 4-chn Digital Ouput; Rail: Right; BoxNextB: JSBTIMGW; BoxPrev: CIPRNNJE; PortPrevFull: 1049/B; PortPrevShort: B; Fullname: TIID^Vertex ISC (EtherCAT)^ISC Common R0 (EK1100)^ISC Common R12 (EL2124); BoxAddr: 1050; Disabled: False
B83 = TerminalEL2124: EtherCAT Terminal EL2124 4-chn Digital Ouput; Rail: Right; BoxNextB: BRRMJHXC; BoxPrev: BQHYSPEL; PortPrevFull: 1050/B; PortPrevShort: B; Fullname: TIID^Vertex ISC (EtherCAT)^ISC Common R0 (EK1100)^ISC Common R13 (EL2124); BoxAddr: 1051; Disabled: False
B84 = TerminalEL2124: EtherCAT Terminal EL2124 4-chn Digital Ouput; Rail: Right; BoxNextB: WXCBAILG; BoxPrev: JSBTIMGW; PortPrevFull: 1051/B; PortPrevShort: B; Fullname: TIID^Vertex ISC (EtherCAT)^ISC Common R0 (EK1100)^ISC Common R14 (EL2124); BoxAddr: 1052; Disabled: False
B85 = TerminalEL9011: EtherCAT Terminal EL9011 End; BoxType: TerminalPassive; Rail: Right; BoxPrev: BRRMJHXC; PortPrevShort: B; Fullname: TIID^Vertex ISC (EtherCAT)^ISC Common R0 (EK1100)^ISC Common R15 (EL9011); Disabled: False
V68 = LowNoiseVco_LowNoiseVcoInStruct: LowNoiseVcoInStruct; BoxType: Variable; Instance: H1IscCorner Instance; PLC: H1IscCorner; Task: IscCStd
V144 V146 = CommonMode_CommonModeInStruct: CommonModeInStruct; BoxType: Variable; Instance: H1IscCorner Instance; PLC: H1IscCorner; Task: IscCStd
V145 V147 = CommonMode_CommonModeOutStruct: CommonModeOutStruct; BoxType: Variable; Instance: H1IscCorner Instance; PLC: H1IscCorner; Task: IscCStd
V148 = LowNoiseVco_LowNoiseVcoOutStruct: LowNoiseVcoOutStruct; BoxType: Variable; Instance: H1IscCorner Instance; PLC: H1IscCorner; Task: IscCStd
V150 = DelayLogic_DelayLogicOutStruct: DelayLogicOutStruct; BoxType: Variable; Instance: H1IscCorner Instance; PLC: H1IscCorner; Task: IscCStd
V151 = DelayLogic_DelayLogicOutStructB: DelayLogicOutStruct; BoxType: Variable; Instance: H1IscCorner Instance; PLC: H1IscCorner; Task: IscCStd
